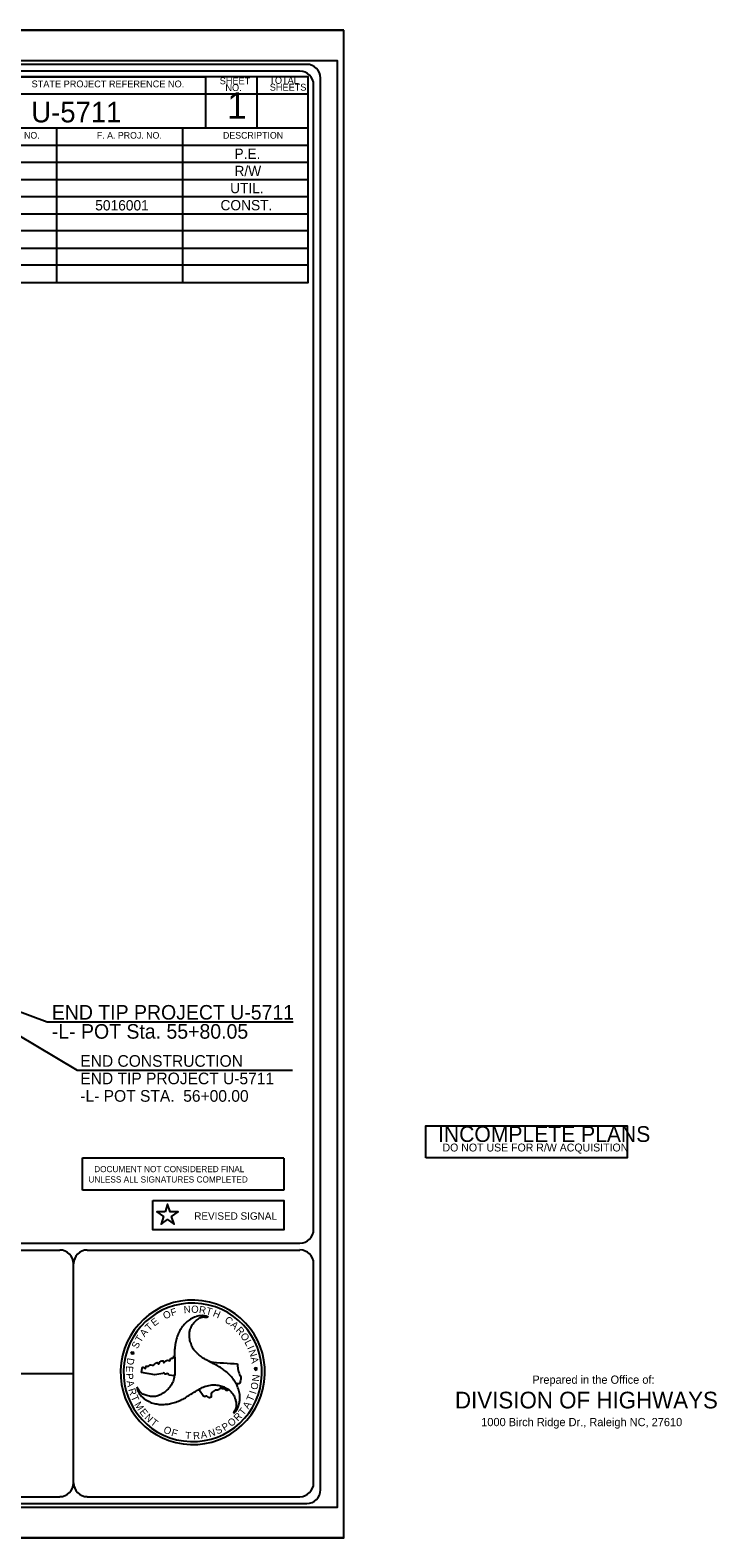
# Model space of a CAD drawing. Extents: x 1750553 to 1763838, y 734059 to 742526.
# Drawn here: x 1760830 to 1763838, y 734561 to 741161 of the extents above; entities that cross this region are included whole.
import ezdxf

# ---------------------------------------------------------------- set-up
doc = ezdxf.new("R2010")
doc.units = 0
for name, color, linetype in [('Prop Grid Mask', 7, 'Continuous'), ('Prop Horizontal Alignment', 7, 'Continuous'), ('Prop RDY Traffic Signal CELL', 7, 'Continuous'), ('Scratch_Level_3', 7, 'Continuous'), ('Sheet Cutting Line CELL', 7, 'Continuous'), ('Sheet PE Seal Cell', 7, 'Continuous'), ('Sheet Plot Border Inside CELL', 7, 'Continuous'), ('Sheet Plot Border Outside CELL', 7, 'Continuous'), ('Sheet Sticker Exception Certification CELL', 7, 'Continuous'), ('Sheet Sticker Incomplete CELL', 7, 'Continuous'), ('Sheet Title CELL', 7, 'Continuous')]:
    doc.layers.add(name, color=color, linetype=linetype)

msp = doc.modelspace()

# ---------------------------------------------------------------- linework, layer by layer
at = {"layer": 'Prop Grid Mask'}
msp.add_lwpolyline([(1761367.7, 736037.2), (1761941.5, 736037.2), (1761941.5, 735909.3), (1761367.7, 735909.3)], close=True, dxfattribs=at)
at = {"layer": 'Prop Horizontal Alignment'}
for p, q in [((1760265.6, 737055.9), (1760904.4, 736819.6)), ((1760904.4, 736819.6), (1761982.4, 736819.6))]:
    msp.add_line(p, q, dxfattribs=at)
at = {"layer": 'Prop RDY Traffic Signal CELL'}
msp.add_lwpolyline([(1761420.8, 735988.3), (1761385.5, 735988.3), (1761414.1, 735967.5), (1761403.1, 735933.8), (1761431.8, 735954.6), (1761460.5, 735933.8), (1761449.5, 735967.5), (1761478.1, 735988.3), (1761442.7, 735988.3), (1761431.8, 736022), (1761420.8, 735988.3)], dxfattribs=at)
at = {"layer": 'Sheet Cutting Line CELL'}
for p, q in [((1752099.6, 741160.9), (1762203.6, 741160.9)), ((1752099.6, 734560.9), (1762203.6, 734560.9)), ((1762200.6, 734560.9), (1752099.6, 734560.9))]:
    msp.add_line(p, q, dxfattribs=at)
at = {"layer": 'Sheet PE Seal Cell'}
for p, q in [((1760282.7, 737056.4), (1761035.9, 736608.2)), ((1761035.9, 736608.2), (1761978.8, 736608.2))]:
    msp.add_line(p, q, dxfattribs=at)
at = {"layer": 'Sheet Plot Border Inside CELL'}
msp.add_lwpolyline([(1752177.6, 734695.6), (1762176.6, 734695.6), (1762176.6, 741026.2), (1752177.6, 741026.2)], close=True, dxfattribs=at)
at = {"layer": 'Sheet Plot Border Outside CELL'}
msp.add_lwpolyline([(1762203.6, 741160.9), (1752099.6, 741160.9), (1752099.6, 734560.9), (1762203.6, 734560.9)], close=True, dxfattribs=at)
at = {"layer": 'Sheet Sticker Exception Certification CELL'}
for p, q in [((1761059.1, 736082.8), (1761059.1, 736223.8)), ((1761059.1, 736223.8), (1761941.1, 736223.8)), ((1761941.1, 736223.7), (1761941.1, 736082.7)), ((1761941.1, 736082.8), (1761059.1, 736082.8))]:
    msp.add_line(p, q, dxfattribs=at)
at = {"layer": 'Sheet Sticker Incomplete CELL'}
msp.add_lwpolyline([(1762563, 736223.8), (1762563, 736364.8), (1763445, 736364.8), (1763445, 736223.8)], close=True, dxfattribs=at)
at = {"layer": 'Sheet Title CELL'}
for p, q in [((1753491.6, 735850.9), (1762011.6, 735850.9)), ((1759761.6, 735820.9), (1760960.2, 735820.9)), ((1761020.2, 734800.9), (1761020.2, 735760.9)), ((1761080.2, 735820.9), (1762011.6, 735820.9)), ((1761608.2, 735529.3), (1761607.6, 735528.7)), ((1761608.2, 735529.3), (1761607.6, 735528.7)), ((1761275.1, 735369.7), (1761271.2, 735373.6)), ((1761271.2, 735373.6), (1761276.6, 735372.8)), ((1761272.8, 735364.7), (1761275.1, 735369.7)), ((1761277.4, 735367.4), (1761272.8, 735364.7)), ((1761276.6, 735372.8), (1761278.8, 735377.7)), ((1761281.5, 735363.6), (1761277.4, 735367.4)), ((1761278.8, 735377.7), (1761280, 735372.4)), ((1761280, 735372.4), (1761285.4, 735371.7)), ((1761285.4, 735371.7), (1761280.5, 735369)), ((1761280.5, 735369), (1761281.5, 735363.6)), ((1761317.1, 735285.3), (1761320.3, 735304)), ((1761616.2, 735332.3), (1761616.2, 735332.3)), ((1761817, 735302.7), (1761811.6, 735303.5)), ((1761811.6, 735303.5), (1761815.6, 735299.7)), ((1761815.6, 735299.7), (1761813.4, 735294.7)), ((1761819.3, 735307.5), (1761817, 735302.7)), ((1761820.5, 735302.3), (1761819.3, 735307.5)), ((1761825.8, 735301.8), (1761820.5, 735302.3)), ((1761821, 735299), (1761825.8, 735301.8)), ((1761821.9, 735293.6), (1761821, 735299)), ((1759696.2, 735281.1), (1761020.2, 735281.1)), ((1761376.3, 735275.1), (1761317.1, 735285.3)), ((1761411.7, 735280.6), (1761376.3, 735275.1)), ((1761462.2, 735269.7), (1761437.4, 735273.2)), ((1761813.4, 735294.7), (1761818, 735297.3)), ((1761818, 735297.3), (1761821.9, 735293.6)), ((1761855.5, 735243.7), (1761855.5, 735243.7)), ((1761591.2, 735178.4), (1761568.7, 735210.5)), ((1761568.7, 735210.5), (1761568.7, 735210.5))]:
    msp.add_line(p, q, dxfattribs=at)
for points in [[(1762041.7, 741010.9), (1753161.5, 741010.9)], [(1762011.6, 740980.9), (1753491.7, 740980.9)], [(1760397.6, 740881.9), (1762047.6, 740881.9), (1762047.6, 740956.9), (1760397.6, 740956.9)], [(1760622.6, 740956.9), (1761597.7, 740956.9), (1761597.6, 740731.9), (1761497.4, 740731.9), (1761497.4, 740056.9), (1762047.6, 740056.9), (1762047.6, 740956.9), (1761822.6, 740956.9), (1761822.7, 740731.9)], [(1762071.6, 735910.9), (1762071.6, 740920.9)], [(1762101.6, 734770.9), (1762101.6, 740950.9)], [(1760397.6, 740656.9), (1762047.6, 740656.9), (1762047.6, 740731.9), (1760397.6, 740731.9)], [(1760397.6, 740056.9), (1760947.5, 740056.9), (1760947.5, 740731.9), (1760622.6, 740731.9)], [(1760397.6, 740506.9), (1762047.6, 740506.9), (1762047.6, 740581.9), (1760397.6, 740581.9)], [(1760397.6, 740356.9), (1762047.6, 740356.9), (1762047.6, 740431.9), (1760397.6, 740431.9)], [(1760397.6, 740206.9), (1762047.6, 740206.9), (1762047.6, 740281.9), (1760397.7, 740281.9)], [(1760397.6, 740056.9), (1762047.6, 740056.9), (1762047.6, 740131.9), (1760397.6, 740131.9)], [(1762071.6, 734800.9), (1762071.6, 735760.9)], [(1753161.6, 734710.9), (1762041.6, 734710.9)], [(1759761.6, 734740.9), (1760960.2, 734740.9)], [(1761080.2, 734740.9), (1762011.6, 734740.9)]]:
    msp.add_lwpolyline(points, dxfattribs=at)
for centre, radius, start, end in [((1762011.6, 740921.2), 60, 0, 90), ((1762041.6, 740951.2), 60, 0, 90), ((1762011.6, 735911.2), 60, 270, 360), ((1760960.2, 735760.9), 60, 0, 90), ((1761080.2, 735760.9), 60, 90, 180), ((1762011.6, 735761.2), 60, 0, 90), ((1761542, 735285.4), 316.3, 352.42113, 172.42113), ((1761542, 735285.4), 303.1, 352.42113, 172.42113), ((1761542, 735285.4), 316.3, 172.42113, 352.42113), ((1761542, 735285.4), 303.1, 172.42113, 352.42113), ((1761803.8, 736989.4), 1667.7, 258.09962, 258.19922), ((1761803.8, 736989.4), 1667.7, 263.53868, 267.74469), ((1760960.2, 734801.3), 60, 270, 360), ((1761080.2, 734801.3), 60, 180, 270), ((1762011.6, 734801.2), 60, 270, 360), ((1762041.6, 734771.2), 60, 270, 360)]:
    msp.add_arc(centre, radius, start, end, dxfattribs=at)
for points in [[(1761607.6, 735528.7), (1761600.8, 735531.5), (1761579.9, 735533.5), (1761557.8, 735529.5), (1761555.8, 735528.7), (1761544.4, 735524.6), (1761532.1, 735517.7), (1761512.9, 735503.9), (1761497.3, 735485.8), (1761491, 735478.1), (1761485.8, 735468.2), (1761475.8, 735447), (1761469.4, 735426.1), (1761464.7, 735401.3), (1761462.1, 735379.3), (1761462.8, 735356.4), (1761463.7, 735333.3), (1761464, 735310.9), (1761464.1, 735287.9), (1761461.2, 735265.5), (1761460.8, 735263.6), (1761453.6, 735240.2), (1761441.2, 735220.6), (1761426.4, 735204.7), (1761418, 735197.6), (1761406.4, 735190.8), (1761399.8, 735186.9), (1761384.6, 735181.5), (1761362.5, 735179.4), (1761341.7, 735183.4), (1761323.7, 735190.6), (1761308.7, 735203.3), (1761297.8, 735220)], [(1761720.3, 735106.2), (1761725.8, 735110.6), (1761738.1, 735127.8), (1761745.7, 735148.9), (1761746.3, 735151), (1761748.1, 735163), (1761748.4, 735177.2), (1761746.2, 735200.7), (1761738.1, 735223.1), (1761734.7, 735232.5), (1761728.6, 735242.1), (1761715.3, 735261.2), (1761700.5, 735277.3), (1761681.3, 735293.7), (1761663.5, 735306.7), (1761643.3, 735317.9), (1761623, 735328.6), (1761603.6, 735339.4), (1761583.3, 735351), (1761565.5, 735364.6), (1761564.1, 735366), (1761547.2, 735383.9), (1761536.5, 735404.6), (1761530, 735425.2), (1761528.4, 735435.9), (1761528.3, 735449.4), (1761527.9, 735457.3), (1761531.1, 735472.9), (1761540.3, 735493.3), (1761554, 735509.2), (1761569.3, 735521.1), (1761587.9, 735527.7), (1761607.6, 735528.7), (1761608.2, 735529.3)], [(1761320.3, 735304), (1761319.9, 735305.9), (1761323.3, 735307.5), (1761331.6, 735302.7), (1761336.6, 735305.9), (1761336.9, 735309.8), (1761341, 735313.1), (1761346.8, 735311.1), (1761353.2, 735317.3), (1761358.4, 735317.9), (1761369, 735316.5), (1761383.2, 735327.4), (1761388.6, 735327.5), (1761389.5, 735324), (1761392.7, 735322.9), (1761399.4, 735332.6), (1761401, 735333.9), (1761411.4, 735336.5), (1761413.8, 735334.3), (1761413.9, 735329.5), (1761415.2, 735328.4), (1761418.7, 735330.3), (1761423.8, 735335.3), (1761432.5, 735338.4), (1761441.5, 735336.1), (1761444.1, 735343.4), (1761455.8, 735349.2), (1761458.7, 735353.3), (1761459.8, 735357.6)], [(1761462.7, 735357), (1761462.8, 735356.4), (1761463.7, 735333.3), (1761464, 735310.9), (1761464.1, 735287.9), (1761462.1, 735269.7)], [(1761732.9, 735236.2), (1761728.6, 735242.1), (1761715.3, 735261.2), (1761700.5, 735277.3), (1761681.3, 735293.7), (1761663.5, 735306.7), (1761643.3, 735317.9), (1761623, 735328.6), (1761616.2, 735332.3)], [(1761738.2, 735323), (1761739.8, 735301.5), (1761747.5, 735275.4), (1761752.8, 735261), (1761751.1, 735249.4), (1761746.5, 735235.9), (1761733, 735236.3)], [(1761297.8, 735220), (1761299.1, 735212.7), (1761307.8, 735193.5), (1761322.2, 735176.3), (1761323.8, 735175.1), (1761333.3, 735167.2), (1761345.4, 735160.1), (1761366.9, 735150.2), (1761390.2, 735146), (1761400.1, 735144.2), (1761411.8, 735144.7), (1761434.6, 735146.8), (1761455.8, 735151.4), (1761479.8, 735159.9), (1761499.9, 735168.6), (1761519.7, 735180.7), (1761539.1, 735193.1), (1761558.4, 735204.5), (1761578.4, 735215.9), (1761599.1, 735224.8), (1761601.4, 735225.3), (1761625.2, 735230.9), (1761648.1, 735229.9), (1761669.1, 735225.2), (1761679.8, 735221.4), (1761691.1, 735214.5), (1761698.3, 735211), (1761710.2, 735200.4), (1761723, 735182.4), (1761730.1, 735162.5), (1761732.8, 735143.1), (1761729.3, 735123.8), (1761720.3, 735106.2)], [(1761437.4, 735273.2), (1761435.6, 735278.1), (1761431, 735280.1), (1761424, 735277.6), (1761419.1, 735278.5), (1761414.2, 735283.1), (1761411.7, 735280.6)], [(1761568.7, 735210.5), (1761578.4, 735215.9), (1761599.1, 735224.8), (1761601.4, 735225.3), (1761625.2, 735230.9), (1761648.1, 735229.9), (1761669.1, 735225.2), (1761679.8, 735221.4), (1761691.1, 735214.5), (1761697.8, 735211.2)], [(1761697.6, 735211.1), (1761694, 735206), (1761689.2, 735206.2), (1761681.9, 735213.9), (1761671.5, 735213.3), (1761667.2, 735216.6), (1761664.1, 735217.1), (1761655.5, 735208.8), (1761645.2, 735207.9), (1761627.4, 735198.1), (1761623.1, 735191.6), (1761622.3, 735176.4), (1761617.9, 735173.9), (1761613.2, 735175.3), (1761603.6, 735180.6), (1761591.2, 735178.4)]]:
    msp.add_spline(points, degree=3, dxfattribs=at)

# ---------------------------------------------------------------- texts
at = {"layer": 'Prop Horizontal Alignment'}
for s, p in [('END TIP PROJECT U-5711', (1760924.9, 736829.6)), ('-L- POT Sta. 55+80.05', (1760924.9, 736746))]:
    msp.add_text(s, height=63.75, rotation=0.00011, dxfattribs=at).set_placement(p)
at = {"layer": 'Scratch_Level_3'}
for s, height, p in [('U-5711    ', 90, (1760835, 740757.1)), ('P.E.', 45, (1761724.8, 740597.2)), ('R/W', 45, (1761724.9, 740522.2)), ('UTIL.', 45, (1761705.9, 740447.2)), ('5016001', 45, (1761115.1, 740371.7)), ('CONST.', 45, (1761663.6, 740372.3))]:
    msp.add_text(s, height=height, dxfattribs=at).set_placement(p)
at = {"layer": 'Sheet PE Seal Cell'}
for s, height, p in [('END CONSTRUCTION', 51, (1761049.6, 736623)), ('END TIP PROJECT U-5711', 51, (1761049.6, 736546.5)), ('-L- POT STA.  56+00.00', 51, (1761049.6, 736470)), ('REVISED SIGNAL', 32.5, (1761548.7, 735953.6))]:
    msp.add_text(s, height=height, rotation=360, dxfattribs=at).set_placement(p)
at = {"layer": 'Sheet Sticker Exception Certification CELL'}
for s, p in [('DOCUMENT NOT CONSIDERED FINAL', (1761110.3, 736161.7)), ('UNLESS ALL SIGNATURES COMPLETED', (1761085.1, 736116.4))]:
    msp.add_text(s, height=27, dxfattribs=at).set_placement(p)
at = {"layer": 'Sheet Sticker Incomplete CELL'}
for s, height, p in [('INCOMPLETE PLANS', 69.12, (1762616.7, 736294)), ('DO NOT USE FOR R/W ACQUISITION', 34.56, (1762636.2, 736252.3))]:
    msp.add_text(s, height=height, dxfattribs=at).set_placement(p)
at = {"layer": 'Sheet Title CELL'}
for s, height, rotation, p in [('STATE PROJECT REFERENCE NO.', 29.999, 360, (1760836.2, 740910.4)), ('SHEET', 30, 360, (1761660.3, 740923.9)), ('NO.', 30, 360, (1761685.2, 740894.2)), ('TOTAL', 30, 360, (1761877.5, 740926)), ('SHEETS', 30, 360, (1761879.5, 740896)), ('1', 116.1, 360, (1761692.7, 740773)), ('STATE PROJ. NO.', 28.8, 360, (1760544.3, 740686)), ('F. A. PROJ. NO.', 28.8, 360, (1761122.1, 740686)), ('DESCRIPTION', 28.8, 360, (1761674.7, 740686)), ('F', 31.6, 17.49185, (1761450.7, 735530.2)), ('N', 31.5, 5.40491, (1761503.9, 735543.9)), ('O', 31.6, 357.9068, (1761534.6, 735546.6)), ('R', 31.5, 351.29687, (1761567.9, 735545.4)), ('T', 31.6, 344.64724, (1761597.8, 735540.8)), ('T', 31.5, 43.6937, (1761351.4, 735464.2)), ('E', 31.4, 36.57807, (1761373.8, 735485.4)), ('O', 31.6, 24.63869, (1761420.3, 735516.5)), ('H', 31.5, 337.56252, (1761627.5, 735532.4)), ('C', 31.4, 325.22017, (1761679.1, 735508)), ('A', 31.5, 317.72314, (1761704.9, 735489.9)), ('T', 31.6, 57.80123, (1761314, 735413.1)), ('A', 31.6, 50.74892, (1761330.7, 735438.9)), ('R', 31.5, 311.35919, (1761728.8, 735468.2)), ('O', 31.6, 304.23959, (1761748.7, 735445.5)), ('S', 31.5, 64.17738, (1761300.8, 735386.1)), ('L', 31.5, 298.00591, (1761767.6, 735417.7)), ('I', 31.6, 294.01657, (1761779.9, 735393.4)), ('N', 31.5, 288.31647, (1761785.9, 735379.2)), ('E', 31.4, 266.56202, (1761250.6, 735314.6)), ('D', 31.5, 260.27413, (1761256.3, 735350.4)), ('A', 31.5, 280.88449, (1761795.4, 735349.8)), ('P', 31.5, 274.09441, (1761249.1, 735280.4)), ('A', 31.5, 280.68699, (1761251.6, 735246.8)), ('O', 31.4, 77.38125, (1761824.4, 735206.9)), ('N', 31.5, 84.62926, (1761832.4, 735244.1)), ('Prepared in the Office of:', 35.996, 360, (1763029.8, 735235.4)), ('R', 31.5, 287.75562, (1761258.9, 735210.2)), ('T', 31.5, 294.40616, (1761269.8, 735177.1)), ('T', 31.5, 66.59571, (1761804.4, 735154.8)), ('I', 31.6, 72.24562, (1761818.4, 735187.5)), ('DIVISION OF HIGHWAYS', 73.123, 360, (1762690.7, 735127.5)), ('M', 31.5, 301.6412, (1761285.1, 735144.7)), ('E', 31.5, 309.10797, (1761306.7, 735110.9)), ('N', 31.6, 316.07951, (1761328.4, 735084.8)), ('R', 31.6, 45.32446, (1761739.7, 735068.9)), ('T', 31.4, 51.42425, (1761764, 735094.1)), ('A', 31.6, 59.51129, (1761785.8, 735122.4)), ('T', 31.5, 322.92151, (1761354.3, 735060.3)), ('O', 31.5, 336.2252, (1761410.6, 735023.4)), ('F', 31.5, 343.39043, (1761445.7, 735008.5)), ('N', 31.4, 17.04104, (1761615.6, 735001.7)), ('S', 31.4, 24.25151, (1761649.5, 735012.8)), ('P', 31.5, 31.44336, (1761681.2, 735027.3)), ('O', 31.6, 38.13535, (1761709.9, 735045.2)), ('1000 Birch Ridge Dr., Raleigh NC, 27610', 36, 360, (1762805.8, 735049.8)), ('T', 31.4, 356.29966, (1761508.6, 734994.1)), ('R', 31.6, 3.25628, (1761544.3, 734992.2)), ('A', 31.4, 10.00941, (1761579, 734994.7))]:
    msp.add_text(s, height=height, rotation=rotation, dxfattribs=at).set_placement(p)

doc.saveas('drawing.dxf')
